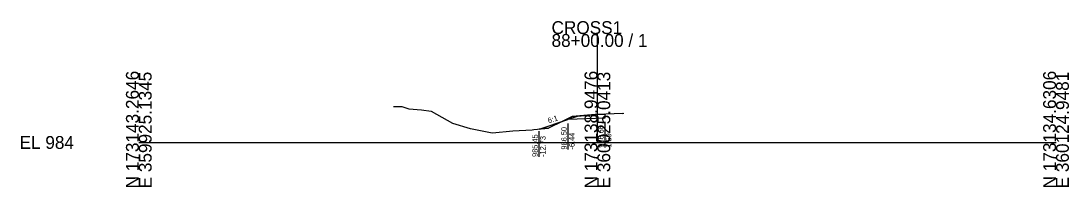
# Model space of a CAD drawing. Extents: x -26 to 1403, y -10 to 11027.
# Drawn here: x -25.7 to 202.8, y 2990.3 to 3026.5 of the extents above; entities that cross this region are included whole.
import ezdxf

# ---------------------------------------------------------------- set-up
doc = ezdxf.new("R2010")
doc.units = 0
for name, color, linetype in [('Default', 7, 'Continuous'), ('P_E_XS_Ground', 7, 'Continuous'), ('P_XS', 7, 'Continuous'), ('P_XS_EAR_CommonGrnd', 7, 'Continuous'), ('P_XS_Lane', 7, 'Continuous'), ('P_XS_Rock', 7, 'Continuous')]:
    doc.layers.add(name, color=color, linetype=linetype)

msp = doc.modelspace()

# ---------------------------------------------------------------- linework, layer by layer
at = {"layer": 'Default'}
for p, q in [((100, 3000), (100, 3023.61)), ((0, 3000), (100, 3000)), ((100, 3000), (200, 3000))]:
    msp.add_line(p, q, dxfattribs=at)
at = {"layer": 'P_E_XS_Ground'}
for p, q in [((55.52, 3007.87), (57.38, 3007.84)), ((57.38, 3007.84), (58.89, 3007.32)), ((58.89, 3007.32), (61.63, 3007.11)), ((61.63, 3007.11), (63.74, 3006.79)), ((63.74, 3006.79), (68.41, 3004.19)), ((94.5, 3005.68), (89.35, 3003.1)), ((99.5, 3006.08), (94.5, 3005.68)), ((100, 3006.1), (99.5, 3006.08)), ((105.48, 3006.32), (100, 3006.1)), ((105.48, 3006.32), (105.74, 3006.36)), ((68.41, 3004.19), (72.26, 3003.08)), ((72.26, 3003.08), (72.7, 3002.98)), ((72.7, 3002.98), (76.66, 3002.14)), ((86.11, 3002.8), (89.35, 3003.1)), ((76.66, 3002.14), (77.14, 3002.09)), ((77.14, 3002.09), (81.56, 3002.52)), ((81.56, 3002.52), (85.79, 3002.79)), ((85.79, 3002.79), (86.11, 3002.8))]:
    msp.add_line(p, q, dxfattribs=at)
at = {"layer": 'P_XS'}
for p, q in [((95.59, 3005.68), (93.56, 3005.01)), ((101.59, 3006.16), (95.59, 3005.68))]:
    msp.add_line(p, q, dxfattribs=at)
at = {"layer": 'P_XS_EAR_CommonGrnd'}
for points in [[(101.59, 3005.33), (93.56, 3005.01), (92.35, 3004.6), (94.5, 3005.68), (99.5, 3006.08), (100, 3006.1), (101.59, 3006.16)], [(87.27, 3002.91), (92.35, 3004.6), (89.35, 3003.1)]]:
    msp.add_lwpolyline(points, close=True, dxfattribs=at)
at = {"layer": 'P_XS_Lane'}
for p, q in [((101.59, 3005.33), (93.56, 3005.01)), ((101.59, 3006.16), (101.59, 3005.33)), ((87.27, 3002.91), (93.56, 3005.01))]:
    msp.add_line(p, q, dxfattribs=at)
at = {"layer": 'P_XS_Rock'}
for p, q in [((93.57, 3004.15), (93.57, 2998.45)), ((101.6, 3004.47), (101.6, 2998.88)), ((87.24, 3002.46), (87.24, 2996.86))]:
    msp.add_line(p, q, dxfattribs=at)

# ---------------------------------------------------------------- texts
at = {"layer": 'Default'}
for s, p in [('CROSS1', (90, 3023.61)), ('88+00.00 / 1', (90, 3020.81)), ('EL 984', (-26, 2998.6))]:
    msp.add_text(s, height=2.8, dxfattribs=at).set_placement(p)
for s, p in [('N 173143.2646', (0, 2990)), ('E 359925.1345', (2.8, 2990)), ('N 173138.9476', (100, 2990)), ('E 360025.0413', (102.8, 2990)), ('N 173134.6306', (200, 2990)), ('E 360124.9481', (202.8, 2990))]:
    msp.add_text(s, height=2.8, rotation=90, dxfattribs=at).set_placement(p)
at = {"layer": 'P_XS_Rock'}
for s, rotation, p in [('6:1', 18.4349, (89.39, 3004.13)), ('986.50', 90, (93.32, 2998.46)), ('986.66', 90, (101.35, 2998.88)), ('985.45', 90, (86.99, 2996.86)), ('-12.73', 90, (88.69, 2996.86)), ('-6.44', 90, (95.02, 2998.46)), ('1.59', 90, (103.05, 2998.88))]:
    msp.add_text(s, height=1.2, rotation=rotation, dxfattribs=at).set_placement(p)

doc.saveas('drawing.dxf')
